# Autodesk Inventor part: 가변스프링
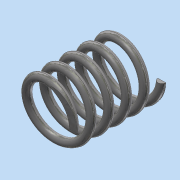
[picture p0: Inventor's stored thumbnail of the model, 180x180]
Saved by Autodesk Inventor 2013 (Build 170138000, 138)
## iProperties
Created: 2019-10
Part Number: 가변스프링
Material: 스테인리스강
Document SubType Name: Modeling
Designer: Administrator
Density: 8.08 g/cm^3
Mass: 147.823 g
Surface Area: 124.156 cm^2
Volume: 18.295 cm^3
Author: Administrator
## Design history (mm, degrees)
sketch "스케치1"
  geometry: L1 (0, 0)-(21, 0); L2 (0, 0)-(0, 67.25); L3 (0, 67.25)-(21, 67.25); C1 r 3 at (21, 0)
  constraints: 6 end point, 2 perpendicular, 1 centre point, 1 coincident, 1 horizontal
  dimensions: "d0" = 21 distance of L1.start L1.end; "d1" = 67.25 distance of L1.start L2.end (derived); "d2" = 6 diameter of C1
feature "코일1" pitch "d3" = 10; turns "d5" = 5; dims "d4" = 67.25 (= d1), "d6" = 0, angle "d7" = 90 deg, angle "d8" = 90 deg, "d9" = 0, "d10" = 0
sketch "스케치2"
  geometry: L1 (67.25, 53.318)-(0, 53.318); L2 (0, 53.318)-(0, -53.318); L3 (0, -53.318)-(67.25, -53.318); L4 (67.25, -53.318)-(67.25, 53.318); 2 further points
  constraints: 8 end point, 2 parallel, 1 coincident, 1 horizontal, 1 midpoint, 1 perpendicular
  dimensions: "d11" = 67.25 distance of L2.end L3.end (= d1); "d13" = 106.63517 distance of L3.end L1.start
extrude "돌출1" sketch "스케치2" stored distance "d14" = 0; taper "d15" = 0 deg
node "솔리드1"
